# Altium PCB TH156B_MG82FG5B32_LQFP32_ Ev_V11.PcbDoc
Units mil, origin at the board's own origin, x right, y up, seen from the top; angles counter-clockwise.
Board outline 2850 x 2110 mil, 2 copper layers (Top Layer, Bottom Layer); 51 components, 51 nets, 266 pads, 99 vias.
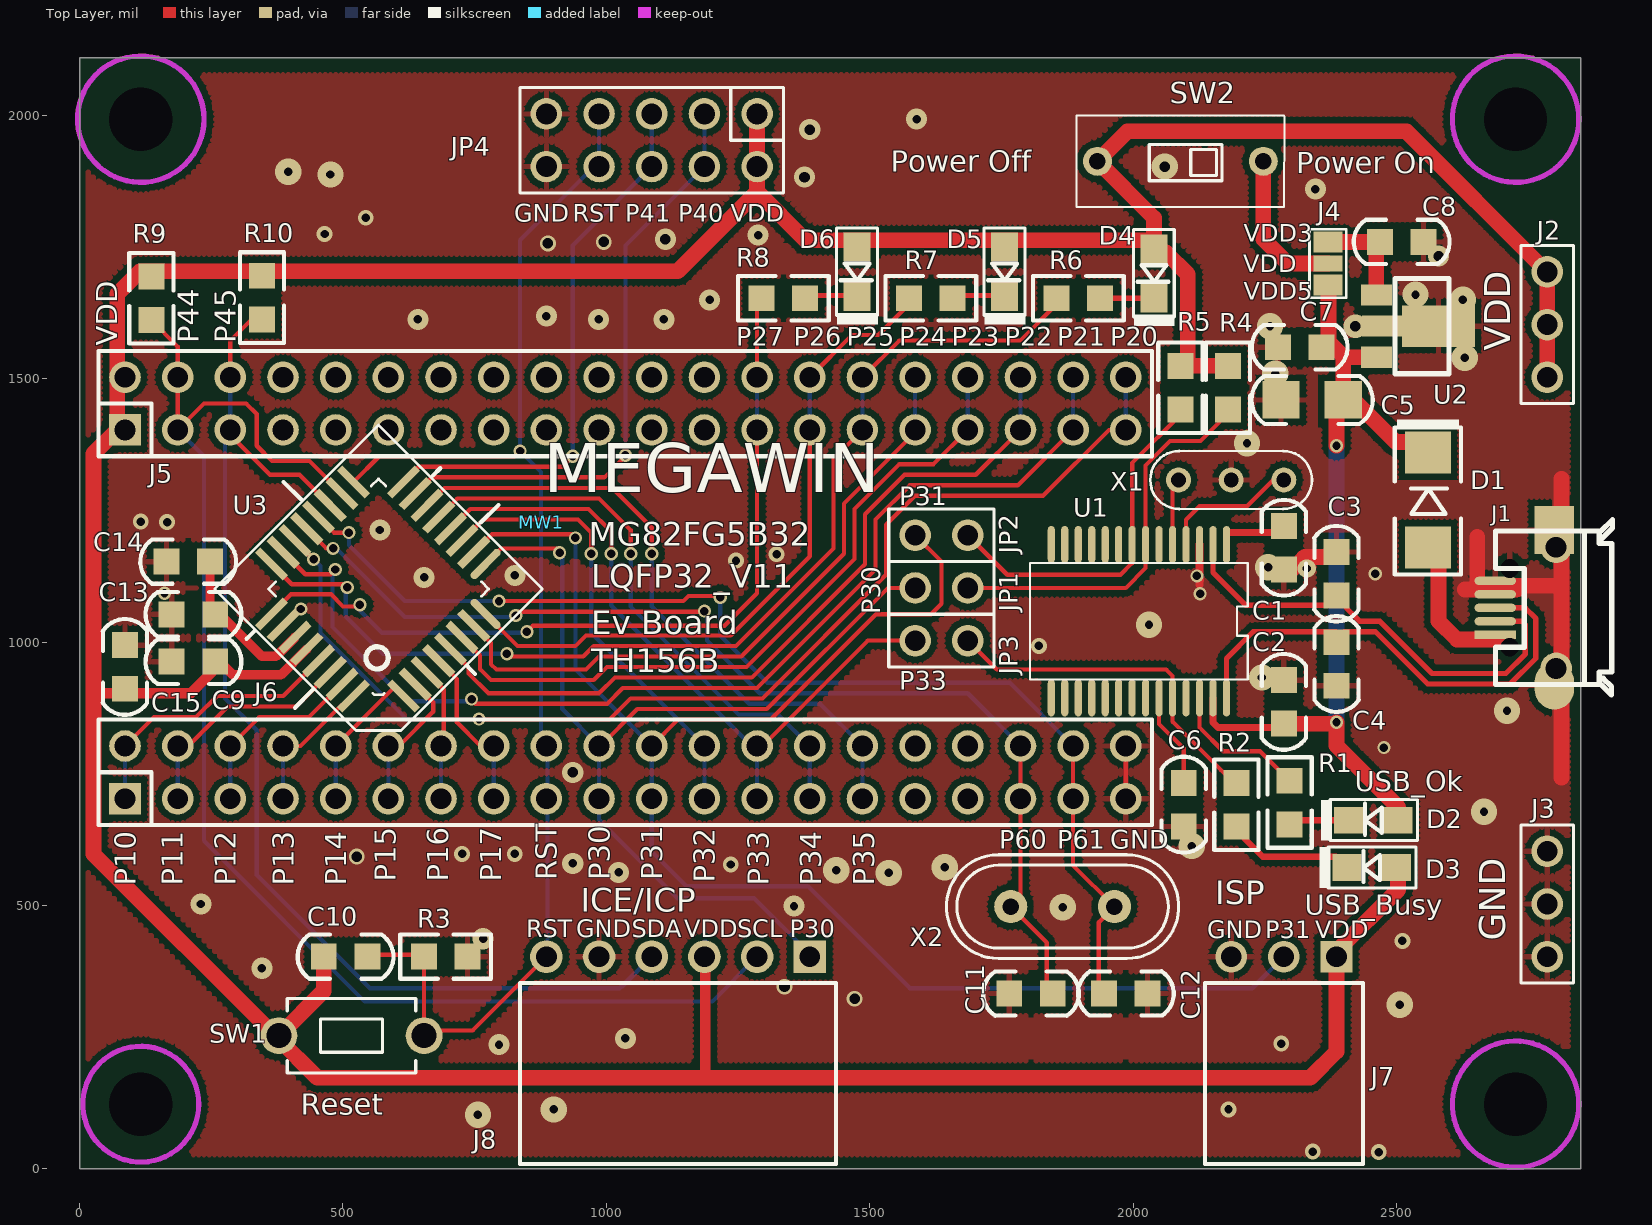
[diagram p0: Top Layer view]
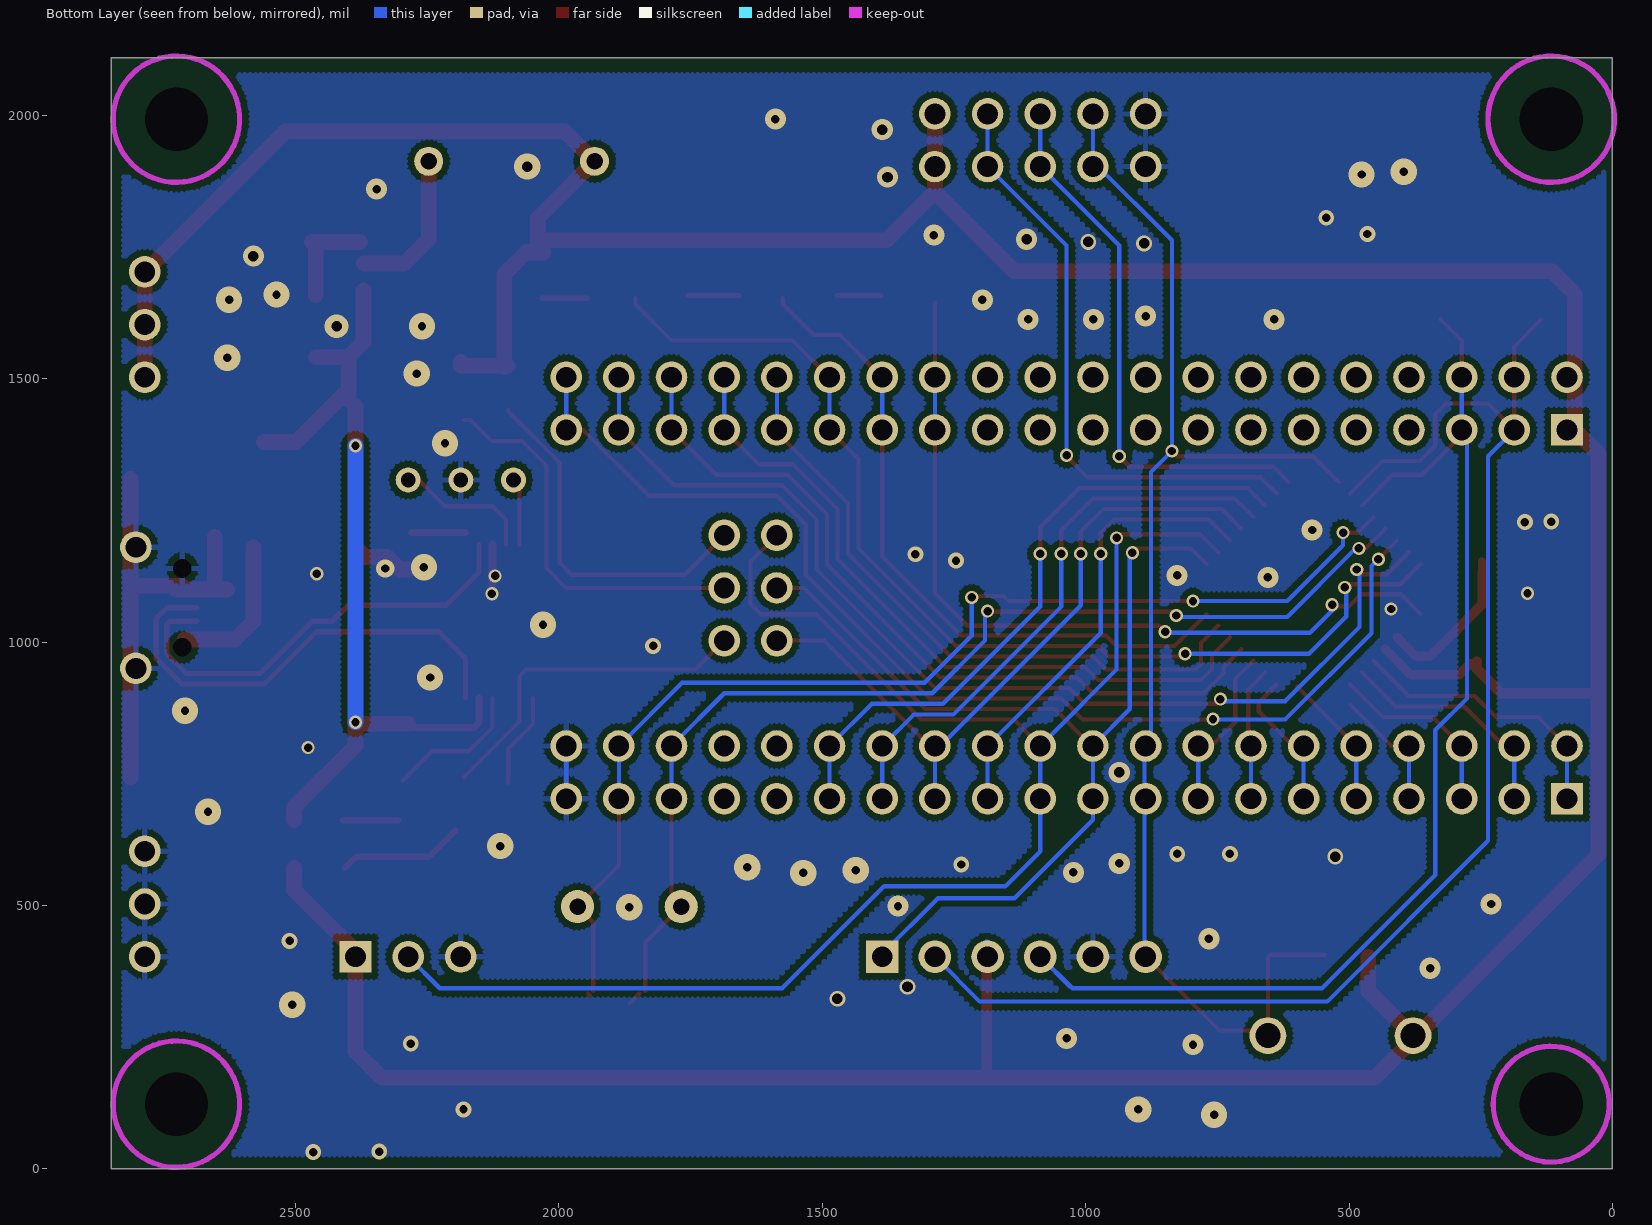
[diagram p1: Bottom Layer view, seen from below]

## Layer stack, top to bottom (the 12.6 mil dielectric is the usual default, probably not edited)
Top Layer: signal copper 1.4
Dielectric: dielectric 12.6, FR-4, Dk 4.8
Bottom Layer: signal copper 1.4

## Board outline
0,0 2850,0 2850,2110 0,2110

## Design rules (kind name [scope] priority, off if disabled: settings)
Clearance 12 [All] p1: gap=12
Clearance 10 [All] p2 off: gap=10
Clearance 6 [All] p3: gap=6
ComponentClearance [All] p1 off: gap=10 collisioncheckmode=3 verticalgap=10 showdistances=FALSE
HoleSize [All] p1: absolutevalues=TRUE maxlimit=500 minlimit=1 maxpercent=80.000 minpercent=20.000
MinimumSolderMaskSliver [All] p1 off: minsoldermaskwidth=10
PolygonConnect VIA [ISVIA] p1: connectstyle=Direct reliefconductorwidth=10 reliefentries=4 polygonreliefangle="90 Angle"
PolygonConnect [All] p2: connectstyle=Relief reliefconductorwidth=10 reliefentries=4 polygonreliefangle="90 Angle"
RoomDefinition TH156B_MG82FG5B32_LQFP32_EV_V10 [InComponentClass('TH156B_MG82FG5B32_LQFP32_EV_V10')] p1: confinementstyle=ConfineIn formatcopy=TRUE lockcomponents=FALSE outline -440,-340 3100,-340 3100,2380 -440,2380
RoutingVias [All] p1: holewidth=16 width=25 viastyle="Through Hole" minholewidth=16 minwidth=24 maxholewidth=28 maxwidth=50
SilkToSilkClearance [All] p1 off: silktosilkclearance=10
SilkscreenOverComponentPads [All] p1 off: minsilkscreentomaskgap=10
SolderMaskExpansion [All] p1 off: expansion=4
Width [All] p1: maxlimit=200 minlimit=6 preferedwidth=10
23 further rules are at their usual default settings.

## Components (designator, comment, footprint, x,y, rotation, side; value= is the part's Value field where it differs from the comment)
C1 "4.7uF" 0805C 2286.34,1179.34 r270 top
C2 "0.1uF" 0805C 2286.34,886.66 r270 top
C3 "15pF" 0805C 2386.34,1130 r90 top
C4 "15pF" 0805C 2386.34,958.66 r270 top
C5 "4.7uF" 1206C 2340,1460 r180 top
C6 "0.1uF" 0805C 2096.34,691.66 r90 top
C7 "0.1uF" 0805C 2316.34,1560 r180 top
C8 "4.7uF" 0805C 2510,1760 r0 top
C9 "0.1uF" 0805C 216.34,963 r0 top
C10 "1u" 0805C 505,403 r0 top
C11 "NC" 0805C 1806.34,333 r180 top
C12 "NC" 0805C 1986.34,333 r0 top
C13 "4.7uF" 0805C 216.34,1053 r180 top
C14 "0.1uF" 0805C 206.34,1153 r0 top
C15 "NC" 0805C 86.34,953 r90 top
D1 "1N5817" D5817_SMD_1 2560,1270 r270 top
D2 "Yellow" 0805D 2456.34,662 r180 top
D3 "Red" 0805D 2453.26,572 r180 top
D4 "Green" 0805D 2040,1700 r270 top
D5 "Red" 0805D 1756.34,1703 r270 top
D6 "Green" 0805D 1476.34,1703 r270 top
J1 "Micro USB母座" JACK_USB_SMD290X220P065 2687.8,1065.28 r180 top
J2 "*" PS3P254 2786.34,1503 r90 top
J3 "*" PS3P254 2786.34,603 r270 top
J4 "*" JUMP3_SMD 2370,1719 r90 top
J5 "*" PS20X2P254 86.34,1403 r0 top
J6 "*" PS20X2P254 86.34,703 r0 top
J7 "*" PS3P254f_90 2386.34,403 r180 top
J8 "*" PS6P254F_90 1386.34,403 r180 top
JP1 "JUMPER2" PS2P254 1586.34,1103 r0 top
JP2 "JUMPER2" PS2P254 1586.34,1203 r0 top
JP3 "JUMPER2" PS2P254 1586.34,1003 r0 top
JP4 "CON5X2" PS5X2P254 1286.34,2003 r180 top
MW1 "MW-A4" MEGAWIN_T 876.34,1228 r0 top
R1 "1K" 0805R 2297.34,695.66 r270 top
R2 "1K" 0805R 2196.34,691.66 r270 top
R3 "47K" 0805R 695,403 r180 top
R4 "4.7K" 0805R 2180,1483 r270 top
R5 "4.7K" 0805R 2090,1483 r270 top
R6 "1K" 0805R 1896.34,1653 r0 top
R7 "1K" 0805R 1616.34,1653 r0 top
R8 "1K" 0805R 1336.34,1653 r0 top
R9 "4.7K" 0805R 136.34,1653 r90 top
R10 "4.7K" 0805R 346.34,1654.34 r90 top
SW1 "SW TACT-SPST" SW_T_2P 516.34,253 r0 top
SW2 "-" DIP2_SW 2247.38,1913 r180 top
U1 "MA101_TSSOP28" SSOP28_220P065 2011.18,1039.85 r180 top
U2 "AIC1734-33(SOT-89)" SOT89 2461.89,1600 r270 top
U3 "MG82FG5B32_LQFP32" QFP32_7X7p080 567.66,1101.13 r135 top locked
X1 "6MHz" X3P 2286.34,1308 r180 top
X2 "NC" X49U 1866.34,498 r180 top

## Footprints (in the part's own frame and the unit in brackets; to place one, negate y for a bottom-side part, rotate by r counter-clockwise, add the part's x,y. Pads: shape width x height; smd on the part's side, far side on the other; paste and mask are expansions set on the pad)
0805C [mm]
  rect 1.25x1.25 smd: 1(-1.05,0) 2(1.05,0)
  silkscreen extent -2.31,-1.07 2.31,1.07
0805D [mm]
  rect 1.4x1.3 smd: 1(-1.192,0) 2(1.192,0)
  silkscreen extent -2.12,-1 2.53,0.98
0805R [mm]
  rect 1.25x1.25 smd: 1(-1.05,0) 2(1.05,0)
  silkscreen extent -2.18,-1.07 2.18,1.07
1206C [mm]
  rect 1.8x1.8 smd: 1(-1.5,0) 2(1.5,0)
  silkscreen extent -2.92,-1.15 2.92,1.16
D5817_SMD_1 [mil]
  rect 80x86.61 smd: 1(90,0) 2(-90,0)
  silkscreen extent -153,-63 142,63
DIP2_SW [mm]
  round 1.4 hole 0.8: 1(0,0) 2(8,0)
  silkscreen extent -1.02,-2.2 9.02,2.2
JACK_USB_SMD290X220P065 [mm]
  rect 1.9x1.8 on Mech2: 0(-2.85,-1.15) 0(-2.85,1.15)
  round 0.8 hole 0.9 unplated: 1(-0.7,1.9) 5(-0.7,-1.9)
  rect 2x0.4 smd: 1(0,1.3)
  oval 2x0.4 smd: 2(0,0.65) 3(0,0) 4(0,-0.65) 5(0,-1.3)
  round 1.524 hole 1: 5(-2.931,2.921) 5(-2.931,-2.921)
  oval 1.9x2.3 smd: 5(-2.85,3.75)
  rect 1.9x2.3 smd: 5(-2.85,-3.75)
  silkscreen extent -5.65,-4.25 -0.01,4.2
JUMP3_SMD [mil]
  rect 40x55 smd: 1(-41,0) 3(41,0)
  rect 30x55 smd: 2(0,0)
  silkscreen extent -65,-35 65,35
MEGAWIN_T [mil]
PS2P254 [mil]
  round 60 hole 39.37: 1(0,0) 2(100,0)
  silkscreen extent -50,-50 150,50
PS3P254 [mil]
  round 60 hole 39.37: 1(0,0) 2(100,0) 3(200,0)
  silkscreen extent -50,-50 250,50
PS3P254f_90 [mil]
  rect 60x60 hole 39.37: 1(0,0)
  round 60 hole 39.37: 2(100,0) 3(200,0)
  silkscreen extent -50,50 250,394
PS5X2P254 [mil]
  round 60 hole 39.37: 1(0,0) 2(0,100) 3(100,0) 4(100,100) 5(200,0) 6(200,100) 7(300,0) 8(300,100) 9(400,0) 10(400,100)
  silkscreen extent -50,-50 450,150
PS6P254F_90 [mil]
  rect 62x62 hole 39.37: 1(0,0)
  round 62 hole 39.37: 2(100,0) 3(200,0) 4(300,0) 5(400,0) 6(500,0)
  silkscreen extent -50,50 550,394
PS20X2P254 [mil]
  rect 60x60 hole 39.37: 1(0,0)
  round 60 hole 39.37: 2(0,100) 3(100,0) 4(100,100) 5(200,0) 6(200,100) 7(300,0) 8(300,100) 9(400,0) 10(400,100) 11(500,0) 12(500,100) 13(600,0) 14(600,100) 15(700,0) 16(700,100) 17(800,0) 18(800,100) 19(900,0) 20(900,100) 21(1000,0) 22(1000,100) 23(1100,0) 24(1100,100) 25(1200,0) 26(1200,100) 27(1300,0) 28(1300,100) 29(1400,0) 30(1400,100) 31(1500,0) 32(1500,100) 33(1600,0) 34(1600,100) 35(1700,0) 36(1700,100) 37(1800,0) 38(1800,100) 39(1900,0) 40(1900,100)
  silkscreen extent -50,-50 1950,150
QFP32_7X7p080 [mm]
  rect 1.9x0.38 smd: 1(-4.5,2.8) 2(-4.5,2) 3(-4.5,1.2) 4(-4.5,0.4) 5(-4.5,-0.4) 6(-4.5,-1.2) 7(-4.5,-2) 17(4.5,-2.8) 18(4.5,-2) 19(4.5,-1.2) 20(4.5,-0.4) 21(4.5,0.4) 22(4.5,1.2) 23(4.5,2) 24(4.5,2.8)
  oval 1.9x0.38 smd: 8(-4.5,-2.8)
  oval 0.38x1.9 smd: 9(-2.8,-4.5)
  rect 0.38x1.9 smd: 10(-2,-4.5) 11(-1.2,-4.5) 12(-0.4,-4.5) 13(0.4,-4.5) 14(1.2,-4.5) 15(2,-4.5) 16(2.8,-4.5) 25(2.8,4.5) 26(2,4.5) 27(1.2,4.5) 28(0.4,4.5) 29(-0.4,4.5) 30(-1.2,4.5) 31(-2,4.5) 32(-2.8,4.5)
  silkscreen extent -6.2,-6.95 6.88,6.9
SOT89 [mm]
  rect 1.016x1.5 smd: 1(-1.5,0) 3(1.5,0)
  rect 2x3.5 smd: 2(0,3)
  rect 1.016x2.6 smd: 2(0,0.6)
  silkscreen extent -2.3,0.9 2.3,3.5
SSOP28_220P065 [mil]
  oval 13.5x70 smd: 1(-166.34,-145.67) 2(-140.75,-145.67) 3(-115.16,-145.67) 4(-89.57,-145.67) 5(-63.98,-145.67) 6(-38.39,-145.67) 7(-12.79,-145.67) 8(12.8,-145.67) 9(38.39,-145.67) 10(63.98,-145.67) 11(89.57,-145.67) 12(115.16,-145.67) 13(140.75,-145.67) 14(166.34,-145.67) 15(166.34,145.67) 16(140.75,145.67) 17(115.16,145.67) 18(89.57,145.67) 19(63.98,145.67) 20(38.39,145.67) 21(12.8,145.67) 22(-12.79,145.67) 23(-38.39,145.67) 24(-63.98,145.67) 25(-89.57,145.67) 26(-115.16,145.67) 27(-140.75,145.67) 28(-166.34,145.67)
  silkscreen extent -207,-110 207,110
SW_T_2P [mil]
  round 70 hole 47.24: 1(-137.79,0) 2(137.79,0)
  silkscreen extent -122,-71 122,71
X3P [mm]
  round 1.2 hole 0.711: 1(0,0) 2(5.08,0) 3(2.54,0)
  silkscreen extent -1.36,-1.4 6.44,1.4
X49U [mm]
  round 1.6 hole 0.8: 1(-2.5,0) 2(2.5,0)
  silkscreen extent -5.6,-2.5 5.6,2.5

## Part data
C1 C5 C8 C13 C15: library part CAP
C2 C3 C4 C6 C7 C9 C14: library part "CAP NP"
C10: library part C
C11 C12: library part "C NP"
D1: library part DIODE_ZD, "Schottky Diode"
D2 D3 D4 D5 D6: library part LED
J1: library part CON5, "Connector"
J2 J3 J4 J7: library part CON3
J5 J6: library part CON40A
J8: library part CON6
R1 R2 R4 R5 R6 R7 R8: library part R_Dup1
R3 R9 R10: library part R
SW2: library part SW-2
U2: library part AIC1734-33(SOT-89)_0
X1: library part CRYSTAL_RC
X2: library part CRYSTAL

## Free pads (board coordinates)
  round 40 hole 120 unplated: 0(116.34,123) 0(116.34,1993) 0(2726.34,123) 0(2726.34,1993)

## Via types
v1: diameter 25, hole 16, Top Layer to Bottom Layer, tented both sides, 31 vias
v2: diameter 50, hole 16, Top Layer to Bottom Layer, tented both sides, 21 vias
v3: diameter 40, hole 16, Top Layer to Bottom Layer, tented both sides, 19 vias
v4: diameter 30, hole 16, Top Layer to Bottom Layer, tented both sides, 15 vias
v5: diameter 40, hole 20, Top Layer to Bottom Layer, tented both sides, 5 vias
v6: diameter 30, hole 20, Top Layer to Bottom Layer, tented both sides, 5 vias
v7: diameter 45, hole 20, Top Layer to Bottom Layer, tented both sides, 1 vias
v8: diameter 35, hole 16, Top Layer to Bottom Layer, tented both sides, 1 vias
v9: diameter 50, hole 20, Top Layer to Bottom Layer, tented both sides, 1 vias

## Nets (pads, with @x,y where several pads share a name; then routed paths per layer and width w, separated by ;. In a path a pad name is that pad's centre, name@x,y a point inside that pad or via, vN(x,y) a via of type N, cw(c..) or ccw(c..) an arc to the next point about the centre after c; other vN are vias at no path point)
D+: C4.1 J1.3 U1.28 | length 905.3
  Top Layer w10: U1.28 2177.52,969.18 2228.34,1020 C4.1@2375.01,1020 ; C4.1@2386.34,1015.52 2379.49,1015.52 C4.1@2375.01,1020 ; C4.1@2386.34,1020 C4.1@2375.01,1020 ; C4.1@2400,1020 2460,1020 2559.45,920.55 2715.8,920.55 2764.8,969.55 2764.8,1045.2 2744.72,1065.28 J1.3
D-: C3.1 J1.2 U1.2 | length 842.2
  Top Layer w10: U1.2 2151.93,1132.41 2214.34,1070 C3.1@2386.34,1070 ; C3.1@2400,1070 2430,1040 2468.28,1040 2567.73,940.55 2707.51,940.55 2744.8,977.84 2744.8,1033.12 2738.23,1039.69 J1.2
GND_POWER: C1.2 C2.1 C3.2 C4.2 C5.2 C6.1 C7.2 C8.2 C9.1 C11.2 C12.2 C13.2 C14.1 C15.2 J1.4 J1.5 J3.1 J3.2 J3.3 J6.39 J6.40 J7.3 J8.5 JP4.9 JP4.10 R3.1 U1.3 U2.2 U3.26 X1.3 | length 1253.9
  Top Layer w8: J6.39 J6.40
  Top Layer w15: 2126.34,1109 v1@2126.34,1119 ; U1.3 2126.34,1126 v1@2126.34,1119 ; v1@2127.34,1118 v1@2126.34,1119
  Top Layer w30: C1.2 2302.34,1138 2317.17,1152.83 2326.34,1162 2330,1162 2367.66,1162 2381.67,1176.01 C3.2@2386.34,1180.68 ; 2630,1100.32 2687.8,1100.32 2727.09,1100.32 ; 2653.66,1102.91 2653.66,1116.46 2653.66,1200 ; 2716.34,1107.32 2813.43,1107.32 ; 2813.66,743 2813.66,917.64 2813.66,950.28 2813.66,1180.28 2813.66,1212.91 2813.66,1310
  Bottom Layer w8: J6.39 J6.40
  other v1: 2476.34,800 420.34,1063 2127.34,1092 161.34,1093 2121.34,1126 2460,1130
  other v2: 756.34,103 900.34,113 2506.34,312 1866.34,497 1536.34,562 1436.34,567 1642.34,573 2111.34,613 2666.34,678 2710,870 2244.73,933 2030.34,1033 2256.34,1142 2216.34,1378 2270,1510 2630,1540 2260,1600 2626.34,1650 2536.34,1660 476.34,1888 396.34,1893
  other v3: 796.34,236 1036.34,248 346.34,381 766.34,437 1356.34,499 230.34,503 1023.34,563 936.34,580 654.34,1123 826.34,1127 570.34,1213 642.34,1613 985.34,1613 1109.34,1613 886.34,1619 1196.34,1650 1288.34,1773 2346.34,1860 1589.34,1993
  other v4: 2466.34,32 2341.34,33 2181.34,113 2281.34,238 2511.34,433 1236.34,578 726.34,598 826.34,598 1821.34,993 1246.34,1155 1323.34,1167 166.34,1228 116.34,1229 465.34,1775 543.34,1806
  other v5: 936.34,753 2580,1733 1112.34,1765 1376.34,1883 1386.34,1973
  other v6: 1471.34,323 1338.34,346 526.34,593 889.34,1757 995.34,1760
  other v7: 2422.33,1600
  other v8: 2330,1140
  other v9: 2060,1903
MA101_RX: JP2.2 R5.2 U1.8 | length 683.4
  Top Layer w8: JP2.2 1761.34,1128 1976.34,1128 1998.39,1150.05 U1.8 1998.39,1340.05 2095,1436.66 2096.34,1438 R5.2@2096.34,1440.66
MA101_TX: JP1.2 R4.2 U1.7 | length 740
  Top Layer w8: JP1.2 1986.34,1103 2023.98,1140.64 U1.7 2023.98,1335.64 2070.34,1382 2128.34,1382 2168.34,1422 R4.2@2180,1422
NetC1_1: C1.1 U1.1 | length 102.5
  Top Layer w13: U1.1@2177.52,1208 C1.1@2280,1208
NetC6_2: C6.2 U1.23 | length 180.6
  Top Layer w8: U1.23 2049.57,844.77 2096.34,798 C6.2
NetC13_1: C13.1 C14.2 U3.27 | length 298.5
  Top Layer w15: C14.2@247.68,1133 C14.2
  Top Layer w18: C14.2@247.68,1133 247.68,1071.66 262.01,1057.33 346.34,973 372.71,973 U3.27
NetD1_1: D1.1 J1.1 | length 284.5
  Top Layer w30: D1.1@2580,1180 2580,1040 2615,1005 2687.8,1005 J1.1@2710,1005
NetD2_2: D2.2 R1.2 | length 104.4
  Top Layer w12: R1.2@2305.01,662 D2.2
NetD3_2: D3.2 R2.2 | length 239.4
  Top Layer w12: R2.2@2196.34,643 2246.34,593 2385.34,593 D3.2
NetD4_2: D4.2 R6.2 | length 85.6
  Top Layer w10: R6.2@1946.34,1653 D4.2@2031.92,1653
NetD5_2: D5.2 R7.2 | length 96.9
  Top Layer w10: R7.2@1657.95,1658 D5.2@1754.87,1658
NetD6_2: D6.2 R8.2 | length 83.8
  Top Layer w10: R8.2@1387.95,1658 D6.2@1471.79,1658
NetJ4_2: J4.2 SW2.1 | length 289.3
  Top Layer w30: SW2.1 2247.38,1765.62 2294,1719 J4.2
NetU1_4: U1.4 X1.1 | length 263.8
  Top Layer w8: U1.4 2100.75,1232.41 2126.34,1258 2216.34,1258 2266.34,1308 X1.1
NetU1_5: U1.5 X1.2 | length 127.1
  Top Layer w8: U1.5 2075.16,1296.82 X1.2
P10: J6.1 J6.2 U3.29 | length 534.2
  Top Layer w8: J6.2 141.34,858 221.34,858 261.34,898 386.8,898 U3.29
  Bottom Layer w8: J6.1 J6.2
P11: J6.3 J6.4 U3.30 | length 447.2
  Top Layer w8: J6.4 206.34,803 281.34,878 411.34,878 U3.30
  Bottom Layer w8: J6.3 J6.4
P12: J6.5 J6.6 U3.31 | length 360.3
  Top Layer w8: J6.6 341.34,858 435.88,858 U3.31
  Bottom Layer w8: J6.5 J6.6
P13: J6.7 J6.8 U3.32 | length 271
  Top Layer w8: J6.8@414.07,803 J6.8 419.33,803 U3.32@497.33,881
  Bottom Layer w8: J6.7 J6.8
P14: J6.9 J6.10 U3.1 | length 259.1
  Top Layer w8: J6.10 598.11,914.78 U3.1@598.84,915.5
  Bottom Layer w8: J6.9 J6.10
P15: J6.11 J6.12 U3.2 | length 278.2
  Top Layer w8: J6.12 606.34,803 671.34,868 671.34,886.09 U3.2
  Bottom Layer w8: J6.11 J6.12
P16: J6.13 J6.14 U3.3 | length 254.7
  Top Layer w8: U3.3 691.34,910.64 691.34,808 J6.14
  Bottom Layer w8: J6.13 J6.14
P17: J6.15 J6.16 U3.4 | length 319.7
  Top Layer w8: U3.4 716.34,930.18 716.34,848 761.34,803 J6.16
  Bottom Layer w8: J6.15 J6.16
P20: J5.39 J5.40 U3.22 | length 2165.4
  Top Layer w8: U3.22 v1(444.49,1157.48) ; v1@762.34,853 1006.34,853 1046.34,893 1296.34,893 1531.34,1128 1531.34,1223 1586.34,1278 1829.33,1278 1954.33,1403 J5.39
  Bottom Layer w8: v1(444.49,1157.48) 457.34,1144.64 457.34,1017 621.34,853 v1@751.34,853 ; J5.39 J5.40
  other v1: 758.34,854
P21: J5.37 J5.38 U3.23 | length 2078.2
  Top Layer w8: U3.23 428.43,1129 476.34,1129 v1(485.34,1138) ; v1@751.34,888 746.34,888 751.34,883 1001.34,883 1031.34,913 1286.34,913 1511.34,1138 1511.34,1233 1576.34,1298 1781.34,1298 J5.37
  Bottom Layer w8: v1(485.34,1138) 480.34,1133 480.34,1029 621.34,888 744.34,888 v1@751.34,888 ; J5.37 J5.38
  other v1: 744.34,892
P22: J5.35 J5.36 U3.5 | length 1486.7
  Top Layer w8: U3.5 738.56,952.5 738.56,940.78 776.34,903 986.34,903 1016.34,933 1276.34,933 1491.34,1148 1491.34,1243 1566.34,1318 1701.34,1318 J5.35
  Bottom Layer w8: J5.35 J5.36
P23: J5.33 J5.34 U3.6 | length 1361.4
  Top Layer w8: U3.6 760.51,975.09 760.51,948.83 781.34,928 976.34,928 1001.34,953 1266.34,953 1471.34,1158 1471.34,1253 1556.34,1338 1621.34,1338 J5.33
  Bottom Layer w8: J5.33 J5.34
P24: J5.31 J5.32 U3.7 | length 1238.3
  Top Layer w8: U3.7 781.34,998.8 781.34,958 791.34,948 961.34,948 986.34,973 1256.34,973 1451.34,1168 1451.34,1263 J5.31@1586.34,1398
  Bottom Layer w8: J5.31 J5.32
P25: J5.29 J5.30 R6.1 U3.24 | length 2047.4
  Top Layer w8: U3.24 402.89,1110 506.34,1110 v1@508.34,1108 ; v1(811.34,978) 811.34,973 956.34,973 976.34,993 1246.34,993 1431.34,1178 1431.34,1348 J5.29 ; J5.30 1556.34,1573 1786.34,1573 1855,1641.66 R6.1
  Bottom Layer w8: v1(508.34,1104) 505.34,1101 505.34,1049 576.34,978 v1(811.34,978) ; J5.29 J5.30
P26: J5.27 J5.28 R7.1 U3.8 | length 1308.5
  Top Layer w8: U3.8 831.69,993 941.34,993 961.34,1013 1236.34,1013 1386.34,1163 J5.27 ; J5.28 1466.34,1583 1516.34,1583 1575,1641.66 R7.1
  Bottom Layer w8: J5.27 J5.28
P27: J5.25 J5.26 R8.1 U3.25 | length 1577.1
  Top Layer w8: U3.25 401.63,1091 477.34,1091 500.34,1068 v1@524.34,1068 ; v1(849.34,1020) 860.58,1031.24 1011.34,1031.24 ; v1@851.34,1018 v1@856.34,1018 ; 990.33,1031.24 1011.34,1031.24 ; J5.25 1286.34,1093 1224.58,1031.24 1011.34,1031.24 ; J5.26 R8.1@1286.34,1644.34
  Bottom Layer w8: v1@524.34,1068 526.84,1065.5 574.34,1018 849.34,1018 v1@851.34,1018 ; J5.25 J5.26
  other v1: 532.34,1071
P30/RXD: J6.19 J6.20 J8.1 JP1.1 U3.9 | length 1946.2
  Top Layer w8: U3.9 800.42,1178 v1@906.34,1178 ; J6.20 988.84,800.5 988.84,803 1058.84,873 1304.78,873 1534.78,1103 JP1.1
  Bottom Layer w8: v1@911.34,1173 912.84,1171.5 916.34,1168 916.34,873 J6.20 ; J6.20@971.34,818 J6.20 ; J8.1@1388.34,406 1280.34,514 1135.34,514 986.34,663 J6.19 J6.20
  other v1: 911.34,1170
P31/TXD: J6.21 J6.22 J7.2 JP2.1 U3.10 | length 3123.1
  Top Layer w8: U3.10 782.88,1205 934.34,1205 v1(941.34,1198) ; J6.22 1136.34,853 1312.28,853 1512.28,1053 1616.34,1053 1636.34,1073 1636.34,1153 JP2.1
  Bottom Layer w8: v1(941.34,1198) 941.34,948 J6.22 ; 1006.34,883 J6.22 ; J7.2 2226.34,343 1576.34,343 1382.64,536.7 1152.64,536.7 1086.34,603 J6.21 J6.22
P32: J6.23 J6.24 U3.11 | length 866
  Top Layer w8: U3.11 766.34,1233 946.34,1233 971.34,1208 v1(971.34,1168)
  Bottom Layer w8: v1(971.34,1168) 971.34,1018 J6.24 J6.23
P33: J6.25 J6.26 JP3.1 U3.12 | length 1343.3
  Top Layer w8: U3.12 741.8,1253 966.34,1253 1009.34,1210 v1(1009.34,1168) ; J6.26 1296.61,803 1496.61,1003 JP3.1
  Bottom Layer w8: v1(1009.34,1168) 1009.34,1070 1278.84,800.5 1278.84,795.5 1286.34,788 J6.25
P34: J6.27 J6.28 U3.13 | length 1098.8
  Top Layer w8: U3.13 717.25,1273 986.34,1273 1046.34,1213 v1(1046.34,1168)
  Bottom Layer w8: v1(1046.34,1168) 1046.34,1068 1251.34,863 1326.34,863 J6.28 J6.27
P35: J6.29 J6.30 U3.14 | length 1231.4
  Top Layer w8: U3.14 692.71,1293 1011.34,1293 1086.34,1218 v1(1086.34,1168)
  Bottom Layer w8: v1(1086.34,1168) 1086.34,1068 1271.34,883 1406.34,883 J6.30 J6.29
P40: JP4.3 JP4.4 U3.15 | length 1140.6
  Top Layer w8: U3.15 668.17,1313 996.34,1313 v1@1036.34,1353
  Bottom Layer w8: v1@1036.34,1353 v1(1036.34,1355) 1036.34,1753 JP4.4 JP4.3
P41: JP4.5 JP4.6 U3.16 | length 1053.6
  Top Layer w8: U3.16 643.63,1333 916.34,1333 v1(936.34,1353)
  Bottom Layer w8: v1(936.34,1353) 936.34,1753 JP4.6 JP4.5
P44: J5.3 J5.4 J8.2 R9.1 U3.18 | length 2728
  Top Layer w8: R9.1 186.34,1561.66 J5.4 J5.3 ; J5.3@186.34,1378 J5.3 ; U3.18 436.34,1343.8 365.53,1343.8 336.34,1373 336.34,1433 316.34,1453 236.34,1453 J5.3
  Bottom Layer w8: J5.3 236.34,1353 236.34,623 541.34,318 1201.34,318 J8.2 ; J8.2@1288.34,403 J8.2@1288.34,426
P45: J5.5 J5.6 J8.4 R10.1 U3.19 | length 2310.6
  Top Layer w8: J5.5@286.34,1393 361.34,1318 417.6,1318 U3.19 ; J5.6 286.34,1573 R10.1@326.34,1613
  Bottom Layer w8: J5.6 J5.5 276.34,1393 276.34,893 336.34,833 336.34,558.01 551.35,343 1025.34,343 1085.84,403.5 J8.4@1088.34,406 ; 1029.34,346 J8.4 J8.4@1088.34,405 ; J8.4@1077.84,415.5 J8.4@1088.34,426
P60: C11.1 J6.35 J6.36 U3.21 X2.2 | length 2263.1
  Top Layer w8: U3.21 468.52,1178 v1(481.34,1178) ; v1(828.3,1050.65) 835.39,1057.74 1061.34,1057.74 ; 991.6,1057.74 1061.34,1057.74 ; v1@1186.34,1057.74 1061.34,1057.74 ; J6.36 J6.35 1786.34,516.42 X2.2 1836.34,429.58 C11.1@1836.34,338 ; C11.1 C11.1@1866.34,314.34
  Bottom Layer w8: v1(481.34,1178) 481.34,1173 492.34,1173 617.34,1048 825.65,1048 v1(828.3,1050.65) ; v1@1186.34,1057.74 1191.08,1053 1191.08,1003.26 1291.34,903 1686.34,903 J6.36 J6.35
  other v1: 1186.34,1059
P61: C12.1 J6.37 J6.38 U3.20 X2.1 | length 2291.1
  Top Layer w8: U3.20 483.06,1208 v1(511.34,1208) ; v1(796.34,1078) 1146.34,1078 1156.34,1088 v1@1216.34,1088 ; J6.38 J6.37 1886.34,576.42 X2.1 1935,468.24 C12.1@1935,338 ; C12.1@1941.34,329.34 C12.1
  Bottom Layer w8: v1(511.34,1208) 511.34,1184 617.34,1078 v1(796.34,1078) ; v1(1216.34,1085) 1216.34,1013 1306.34,923 1766.34,923 J6.38 J6.37
RST: C10.2 J6.17 J6.18 J8.6 JP4.7 JP4.8 R3.2 SW1.2 U3.17 | length 2577.2
  Top Layer w8: U3.17 568.98,1353 826.34,1353 v1(836.34,1363) ; C10.2@546.34,406.81 R3.2@649.85,406.81 ; R3.2@654.13,402.53 654.13,263 746.34,263 J8.6 888.34,405 J8.6@888.34,426
  Bottom Layer w8: J6.18@886.34,801 J6.18 876.34,813 876.34,1323 v1(836.34,1363) 836.34,1763 981.34,1908 986.34,1913 JP4.7 ; J8.6@888.34,406 888.34,703 J6.18@888.34,801
USB_BUSY: JP3.2 R2.1 U1.24 | length 782.4
  Top Layer w8: JP3.2 1741.34,948 2062.95,948 2075.16,935.8 U1.24 2075.16,849.18 ; 2166.34,758 2075.16,849.18 ; R2.1@2181.34,743 2075.16,849.18
USB_OK: R1.1 U1.26 | length 269
  Top Layer w8: U1.26 2126.34,838 2171.34,793 2241.34,793 R1.1
VDD: C9.2 C10.1 C15.1 D3.1 D4.1 D5.1 D6.1 J2.1 J2.2 J2.3 J5.1 J5.2 J7.1 J8.3 JP4.1 JP4.2 R4.1 R5.1 R9.2 R10.2 SW1.1 SW2.2 U3.28 | length 8915.7
  Top Layer w18: C9.2@257.68,959.34 270,959.34 291.34,938 382.25,938 U3.28
  Top Layer w20: 31.34,903 86.34,903 211.34,903 257.68,949.34 C9.2@257.68,959.34 ; C9.2 C9.2@259.51,961.17 ; 1188.34,180 1188.34,403 J8.3@1188.34,406
  Top Layer w30: SW1.1 463.66,338.12 C10.1 ; SW1.1@382.74,249.56 SW1.1@382.82,252.9 ; JP4.1 JP4.2 1286.34,1855 ; D4.1@2027,1763 1756.34,1763 1476.34,1763 1378.34,1763 1286.34,1855 ; D4.1@2030,1740 2040,1740 2062.72,1740 2104,1698.72 R5.1@2104,1524.68 ; D4.1 2040,1805.42 SW2.2 1989.42,1970 2519,1970 J2.3@2786,1703 ; R5.1@2097.68,1524.68 R5.1@2104,1524.68 ; R5.1@2104,1523.68 2104,1524.34 R5.1@2104,1524.68 ; R4.1@2186.34,1532 2186.34,1524.68 2180,1524.68 R5.1@2104,1524.68 ; D3.1@2503.26,572 2503.26,529.92 2386.34,413 J7.1 2386.34,223 2336.34,173 451.34,173 374.94,249.4 26.34,598 26.34,1357.91 71.43,1403 71.43,1503 71.43,1660.97 114.79,1704.34 136.34,1704.34 346.34,1704.34 1135.68,1704.34 1286.34,1855 ; J2.1 J2.2 J2.3@2786.34,1702.66 ; J2.3@2786,1703 2786.17,1702.83 J2.3@2786.34,1702.66 ; J2.3@2786,1703 J2.3 J2.3@2786.34,1702.66
  Bottom Layer w20: J8.3@1188.34,405 J8.3@1188.34,426
VDD3: C8.1 J4.3 U2.1 | length 183.8
  Top Layer w30: J4.3@2379,1760 C8.1 ; U2.1 C8.1@2461.89,1753.23
VDD5: C2.2 C5.1 C7.1 D1.2 D2.1 J4.1 U1.27 U2.3 | length 1667.1
  Top Layer w13: U1.27 2151.93,847.41 2161.34,838 2236.34,838 ; 2171.34,838 2236.34,838 ; C2.2@2286.34,838 2236.34,838
  Top Layer w30: C2.2 2383.66,845.32 v1(2386.34,848) 2386.34,803.66 2503.26,686.74 D2.1 ; J4.1@2371.34,1667.66 2371.34,1570 2400.39,1540.94 U2.3 ; v1(2386.34,1373) C5.1@2386.34,1447.28 ; C5.1 C5.1@2399.06,1480 ; 2399.06,1539.61 C5.1@2399.06,1480 ; D1.2@2560,1380 2499.06,1380 2409.06,1470 C5.1@2399.06,1480
  Bottom Layer w30: v1(2386.34,848) v1(2386.34,1373)
pads on no net: J1.0 J5.7 J5.8 J5.9 J5.10 J5.11 J5.12 J5.13 J5.14 J5.15 J5.16 J5.17 J5.18 J5.19 J5.20 J5.21 J5.22 J5.23 J5.24 J6.31 J6.32 J6.33 J6.34 U1.6 U1.9 U1.10 U1.11 U1.12 U1.13 U1.14 U1.15 U1.16 U1.17 U1.18 U1.19 U1.20 U1.21 U1.22 U1.25

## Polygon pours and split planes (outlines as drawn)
GND_POWER on Bottom Layer "Bottom Layer-No Net" (hatched 90Degree grid 10 track 10, remove dead copper, pour order 1001): 16.34,27 2826.34,27 2826.34,2078 16.34,2078
GND_POWER on Top Layer "Bottom Layer-No Net" (hatched 90Degree grid 10 track 10, remove dead copper, pour order 1001): 16.34,27 2826.34,27 2826.34,2078 16.34,2078

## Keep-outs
Keep-Out Layer:
  circle w10: c2726.34,1993 r120
  circle w10: c116.34,123 r110
  circle w10: c116.34,1993 r120
  circle w10: c2726.34,123 r120

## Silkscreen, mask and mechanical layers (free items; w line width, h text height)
Top Overlay:
  text "Power Off" at 1540,1893 h40
  text "Power On" at 2310,1890 h40
  text "GND" at 825.34,1798 h33
  text "RST" at 936.34,1798 h33
  text "P41" at 1036.34,1798 h33
  text "P40" at 1136.34,1798 h33
  text "VDD" at 1236.34,1798 h33
  text "VDD3" at 2210,1760 h33
  text "VDD" at 2209.58,1702 h33
  text "VDD5" at 2210,1650 h33
  text "P44" at 226.34,1568 h40 r90
  text "P45" at 296.34,1568 h40 r90
  text "VDD" at 71.34,1563 h40 r90
  text "P27" at 1246.34,1563 h35
  text "P26" at 1356.34,1563 h35
  text "P25" at 1456.34,1563 h35
  text "P24" at 1556.34,1563 h35
  text "P23" at 1656.34,1563 h35
  text "P22" at 1756.34,1563 h35
  text "P21" at 1856.34,1563 h35
  text "P20" at 1956.34,1563 h35
  text "VDD" at 2716.34,1553 h50 r90
  text "P31" at 1556.34,1260 h35
  text "MG82FG5B32" at 966.34,1183 h45
  text "LQFP32_V11" at 971.34,1103 h45
  text "P30" at 1520,1053 h35 r90
  text "Ev Board" at 971.34,1015.5 h45
  text "TH156B" at 971.34,943 h45
  text "P33" at 1556.34,910 h35
  text "USB_Ok" at 2421.34,717 h38
  text "P60" at 1746.34,608 h35
  text "P61" at 1856.34,608 h35.43
  text "GND" at 1956.34,608 h35.43
  text "RST" at 906.34,548 h40 r90
  text "P30" at 1006.34,548 h40 r90
  text "P31" at 1106.34,548 h40 r90
  text "P15" at 600.29,544.95 h40 r90
  text "P16" at 700.29,544.95 h40 r90
  text "P17" at 800.29,544.95 h40 r90
  text "P32" at 1206.34,543 h40 r90
  text "P10" at 106.34,538 h40 r90
  text "P11" at 196.34,538 h40 r90
  text "P12" at 296.34,538 h40 r90
  text "P13" at 406.34,538 h40 r90
  text "P14" at 506.34,538 h40 r90
  text "P33" at 1308.34,538 h40 r90
  text "P34" at 1408.34,538 h40 r90
  text "P35" at 1508.34,538 h40 r90
  text "ISP" at 2156.34,503 h45
  text "ICE/ICP" at 951.34,488 h45
  text "USB_Busy" at 2326.34,483 h38
  text "RST" at 848.34,440 h33
  text "GND" at 943.34,440 h33
  text "SDA" at 1048.34,440 h33
  text "VDD" at 1148.34,440 h33
  text "SCL" at 1248.34,440 h33
  text "P30" at 1348.34,440 h33
  text "GND" at 2141.34,438 h33
  text "P31" at 2251.34,438 h33
  text "VDD" at 2346.34,438 h33
  text "GND" at 2706.34,433 h50 r90
  text "Reset" at 420,103 h40
Mechanical 1:
  the board outline again, w13
Mechanical 2:
  lines w6: -53.66,303 86.34,303 ; 386.34,2003 386.34,2143 ; 1286.34,2003 1286.34,2143 ; 1486.34,2003 1486.34,2143 ; 2386.34,2003 2386.34,2143 ; 2786.34,603 2926.34,603 ; 2786.34,1503 2926.34,1503

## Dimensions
0,2110 to 0,0 on Top Overlay
0,0 to 2850,0 on Top Overlay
